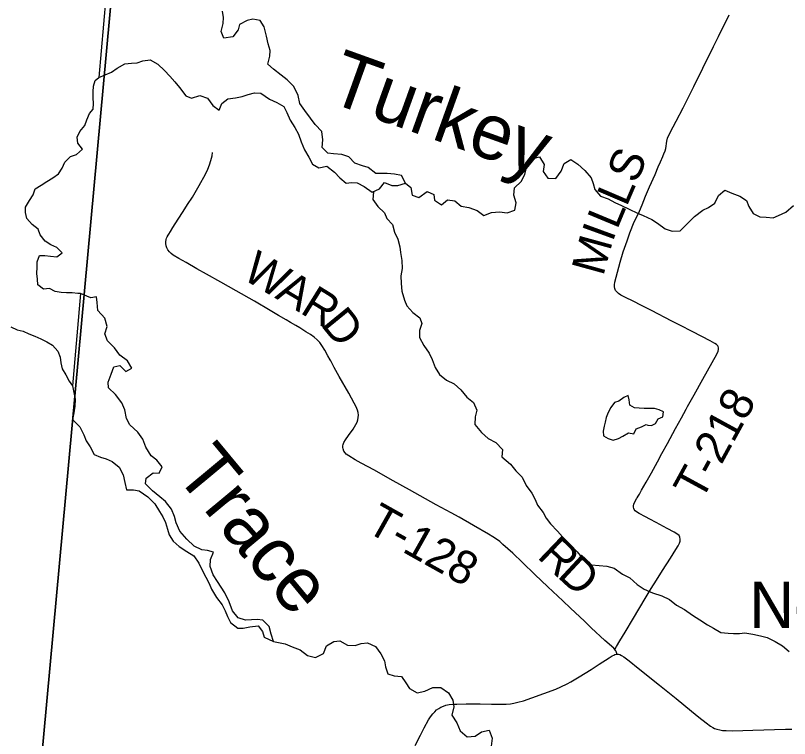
# Model space of a CAD drawing. Extents: x 0 to 34, y 0 to 22.
# Drawn here: x 3.277 to 4.6, y 17.655 to 18.891 of the extents above; entities that cross this region are included whole.
import ezdxf

# ---------------------------------------------------------------- set-up
doc = ezdxf.new("R2010")
doc.units = 0
for name, color, linetype in [('Default', 7, 'Continuous'), ('GM_X_County_Road', 7, 'Continuous'), ('GM_X_Major_Lake', 7, 'Continuous'), ('GM_X_Minor_Lake', 7, 'Continuous'), ('GM_X_Minor_River', 7, 'Continuous'), ('GM_X_Minor_River_Text', 7, 'Continuous'), ('GM_X_Township_Road', 7, 'Continuous'), ('GM_X_Township_Road_Text', 7, 'Continuous'), ('GM_X_Unincorporated_Text', 7, 'Continuous'), ('SH_Cut_Line', 7, 'Continuous')]:
    doc.layers.add(name, color=color, linetype=linetype)

msp = doc.modelspace()

# ---------------------------------------------------------------- linework, layer by layer
at = {"layer": 'Default'}
for points in [[(8.3334, 17.361), (8.3935, 18.0719), (8.4126, 18.2788), (8.4989, 19.2757), (8.562, 20.012), (8.6014, 20.4252), (3.5682, 20.4252), (3.5424, 20.1754), (3.5231, 19.8516), (3.5169, 19.7823), (3.5125, 19.7343), (3.5092, 19.6961), (3.5066, 19.6647), (3.4966, 19.5464), (3.4903, 19.4759), (3.4748, 19.2963), (3.47, 19.2407), (3.2768, 17.1355)], [(3.2768, 17.1355), (3.47, 19.2407)]]:
    msp.add_lwpolyline(points, dxfattribs=at)
at = {"layer": 'GM_X_County_Road'}
for points in [[(3.96, 17.6431), (3.9688, 17.6607), (3.9753, 17.6734), (3.9829, 17.6869), (3.9862, 17.6922), (3.99, 17.6972), (3.9933, 17.701), (3.9966, 17.704), (4.0002, 17.7067), (4.004, 17.7089), (4.0081, 17.7107), (4.0123, 17.7121), (4.0179, 17.7132), (4.0242, 17.714), (4.031, 17.7142), (4.0472, 17.7144), (4.0708, 17.7143), (4.0901, 17.714), (4.105, 17.7139), (4.1155, 17.7142), (4.1228, 17.7147), (4.1283, 17.7156), (4.1355, 17.7172), (4.1449, 17.7199), (4.1591, 17.7245), (4.1801, 17.732), (4.2003, 17.7397), (4.2088, 17.7433), (4.2199, 17.7488), (4.2258, 17.752), (4.2402, 17.7605), (4.2606, 17.7734), (4.2746, 17.7826), (4.2913, 17.7934), (4.2968, 17.7965), (4.2993, 17.7977), (4.3013, 17.7987), (4.3032, 17.7993), (4.3043, 17.7996), (4.3049, 17.7996)], [(4.3049, 17.7996), (4.3063, 17.7996), (4.3073, 17.7995), (4.3099, 17.7988), (4.3128, 17.7974), (4.3165, 17.7949), (4.3255, 17.7882), (4.3409, 17.7756), (4.3778, 17.7463), (4.4058, 17.7236), (4.4325, 17.7022), (4.4449, 17.6919), (4.4571, 17.6823), (4.465, 17.6763), (4.4685, 17.674), (4.4718, 17.6724), (4.4758, 17.671), (4.4805, 17.6698), (4.4853, 17.6691), (4.4915, 17.6687), (4.5032, 17.6686), (4.5374, 17.6696), (4.5927, 17.671), (4.6038, 17.6713)]]:
    msp.add_lwpolyline(points, dxfattribs=at)
at = {"layer": 'GM_X_Major_Lake'}
for p, q in [((3.4324, 18.9394), (3.4192, 18.7851)), ((3.3875, 18.4159), (3.374, 18.2583))]:
    msp.add_line(p, q, dxfattribs=at)
for points in [[(3.5567, 18.7683), (3.5676, 18.7537), (3.5774, 18.7498), (3.5915, 18.7546), (3.6047, 18.75), (3.6137, 18.7377), (3.625, 18.7293), (3.6293, 18.741), (3.6396, 18.7489), (3.6525, 18.7507), (3.6639, 18.7529), (3.6742, 18.7562), (3.6852, 18.7591), (3.6962, 18.7583), (3.7109, 18.7483), (3.7234, 18.7424), (3.7355, 18.7355), (3.7403, 18.7252), (3.7463, 18.7122), (3.7541, 18.6996), (3.7605, 18.6886), (3.7649, 18.6752), (3.7709, 18.6619), (3.7783, 18.6493), (3.7843, 18.6371), (3.7953, 18.6309), (3.8086, 18.6338), (3.8221, 18.6235), (3.8312, 18.6135), (3.8417, 18.6047), (3.8512, 18.6057), (3.8607, 18.6053), (3.8728, 18.5991), (3.8863, 18.5891), (3.8989, 18.595), (3.9077, 18.606), (3.9198, 18.6009), (3.9304, 18.6005), (3.9434, 18.6045), (3.9363, 18.6175), (3.9246, 18.6203), (3.9117, 18.6211), (3.9022, 18.6212), (3.8927, 18.6209), (3.8795, 18.6313), (3.8697, 18.634), (3.8568, 18.6387), (3.8463, 18.6498), (3.8345, 18.6537), (3.8201, 18.6546), (3.8103, 18.6558), (3.8009, 18.6658), (3.8018, 18.6787), (3.8004, 18.6928), (3.7891, 18.705), (3.7812, 18.7157), (3.7715, 18.7287), (3.7625, 18.7406), (3.7596, 18.7543), (3.7525, 18.7699), (3.7408, 18.7814), (3.731, 18.7895), (3.7175, 18.7995), (3.7077, 18.8083), (3.7112, 18.8216), (3.7117, 18.8314), (3.7088, 18.8428), (3.7058, 18.8558), (3.7018, 18.8721), (3.6947, 18.8825), (3.6822, 18.8849), (3.6727, 18.883), (3.6593, 18.8759), (3.6574, 18.8665), (3.6482, 18.8548), (3.633, 18.8526), (3.6281, 18.8637), (3.6317, 18.8777), (3.6321, 18.888), (3.6303, 18.8986)], [(3.4192, 18.7851), (3.4408, 18.7944), (3.4504, 18.8015), (3.4637, 18.8086), (3.4747, 18.8096), (3.4846, 18.8103), (3.4945, 18.814), (3.507, 18.8154), (3.5202, 18.8081), (3.5315, 18.7973), (3.5405, 18.7874), (3.5488, 18.7778), (3.5567, 18.7683)], [(3.4095, 18.731), (3.4097, 18.7409), (3.4096, 18.7508), (3.4095, 18.7607), (3.4097, 18.7702), (3.413, 18.7804), (3.4192, 18.7851)], [(3.3875, 18.4159), (3.3833, 18.416), (3.3734, 18.4174), (3.3639, 18.4173), (3.3545, 18.4179), (3.3446, 18.4197), (3.3345, 18.4245), (3.3246, 18.4233), (3.3149, 18.4311), (3.3144, 18.4407), (3.3128, 18.4502), (3.3138, 18.4608), (3.3137, 18.4703), (3.3174, 18.4809), (3.3269, 18.481), (3.3367, 18.48), (3.347, 18.4789), (3.3566, 18.4855), (3.347, 18.4945), (3.3372, 18.4993), (3.3275, 18.5057), (3.3187, 18.5165), (3.3155, 18.5261), (3.3051, 18.534), (3.2959, 18.5441), (3.2935, 18.5544), (3.2938, 18.5639), (3.3005, 18.5751), (3.3068, 18.5849), (3.3105, 18.595), (3.3206, 18.6012), (3.3302, 18.6074), (3.3403, 18.6136), (3.3503, 18.6206), (3.3563, 18.6303), (3.3611, 18.6408), (3.3709, 18.6504), (3.3808, 18.6536), (3.3909, 18.6628), (3.3829, 18.6729), (3.382, 18.6832), (3.3864, 18.6929), (3.3951, 18.7033), (3.3987, 18.7131), (3.4032, 18.7236), (3.4095, 18.731)], [(3.4292, 18.3471), (3.4335, 18.3596), (3.4291, 18.3737), (3.4174, 18.3871), (3.4164, 18.4004), (3.415, 18.4106), (3.4051, 18.4088), (3.3875, 18.4159)], [(3.2686, 18.359), (3.2795, 18.3538), (3.2897, 18.3516), (3.2994, 18.3472), (3.3096, 18.3428), (3.3201, 18.3387), (3.3302, 18.3335), (3.3399, 18.3275), (3.3491, 18.3174), (3.353, 18.3074)], [(3.374, 18.2583), (3.3785, 18.2355), (3.378, 18.2234), (3.3764, 18.212), (3.374, 18.2006), (3.3864, 18.1883), (3.3935, 18.1742), (3.3976, 18.1643), (3.4043, 18.154), (3.411, 18.141), (3.422, 18.1364), (3.4318, 18.1333), (3.4416, 18.1286), (3.4541, 18.119), (3.4604, 18.106), (3.4633, 18.0927), (3.4663, 18.0805), (3.4784, 18.0804), (3.4879, 18.0788), (3.5026, 18.0684), (3.5146, 18.0566), (3.5228, 18.0436), (3.5284, 18.034), (3.5329, 18.0245), (3.5366, 18.0134), (3.5392, 18.0035), (3.5459, 17.9925), (3.5564, 17.9833), (3.5696, 17.9748), (3.5817, 17.9675), (3.59, 17.9552), (3.5963, 17.9419), (3.6019, 17.9308), (3.6075, 17.9201), (3.6119, 17.9106), (3.6205, 17.8965), (3.6299, 17.8835), (3.6348, 17.8736), (3.6392, 17.8636), (3.6441, 17.8537), (3.6565, 17.8441), (3.666, 17.844), (3.6774, 17.8462), (3.6914, 17.8476), (3.6989, 17.838), (3.7015, 17.8285), (3.7179, 17.8212), (3.7137, 17.8337), (3.71, 17.8467), (3.6995, 17.8574), (3.6896, 17.8586), (3.6802, 17.858), (3.6699, 17.8577), (3.657, 17.8616), (3.6477, 17.8734), (3.6421, 17.8891), (3.6343, 17.9043), (3.6283, 17.9139), (3.6219, 17.9238), (3.6148, 17.9349), (3.6093, 17.9494), (3.6101, 17.9615), (3.6152, 17.9736), (3.605, 17.9767), (3.5951, 17.978), (3.5823, 17.9842), (3.5695, 17.9961), (3.5578, 18.0095), (3.5511, 18.0239), (3.5482, 18.0346), (3.5434, 18.0472), (3.5332, 18.0606), (3.5234, 18.0682), (3.511, 18.0786), (3.4986, 18.0905), (3.4998, 18.1004), (3.5117, 18.1094), (3.5223, 18.1089), (3.5273, 18.1195), (3.5183, 18.131), (3.5085, 18.1383), (3.4995, 18.1532), (3.4944, 18.1669), (3.4857, 18.1791), (3.4718, 18.1914), (3.4666, 18.2021), (3.4637, 18.2169), (3.4585, 18.2291), (3.4476, 18.2432), (3.4356, 18.2547), (3.4349, 18.2646), (3.44, 18.2783), (3.4446, 18.2904), (3.4549, 18.2929), (3.4654, 18.2826), (3.4757, 18.2886), (3.4682, 18.3008), (3.455, 18.3108), (3.4461, 18.3234), (3.4336, 18.3349), (3.4292, 18.3471)], [(3.353, 18.3074), (3.3543, 18.2975), (3.3563, 18.2872), (3.3625, 18.2768), (3.3683, 18.2663), (3.374, 18.2583)]]:
    msp.add_lwpolyline(points, dxfattribs=at)
at = {"layer": 'GM_X_Minor_Lake'}
for points in [[(4.3578, 18.1912), (4.364, 18.1901), (4.3709, 18.1937), (4.3753, 18.202), (4.3833, 18.2053), (4.3846, 18.2136), (4.3771, 18.2171), (4.3688, 18.2196), (4.3604, 18.2194), (4.3513, 18.2196), (4.343, 18.2201), (4.335, 18.2206), (4.3268, 18.2254), (4.3258, 18.2341), (4.3241, 18.2417), (4.3164, 18.2385), (4.3083, 18.2318), (4.3007, 18.2297), (4.2944, 18.2214), (4.2897, 18.2124), (4.2861, 18.2038), (4.2844, 18.1958)], [(4.2844, 18.1958), (4.2828, 18.189), (4.2815, 18.1807), (4.2817, 18.1727), (4.29, 18.1684), (4.2986, 18.1655), (4.3074, 18.168), (4.3151, 18.1724), (4.3243, 18.1779), (4.3334, 18.1759), (4.3377, 18.1849), (4.3465, 18.1881), (4.3546, 18.1918), (4.3578, 18.1912)]]:
    msp.add_lwpolyline(points, dxfattribs=at)
at = {"layer": 'GM_X_Minor_River'}
for points in [[(3.9434, 18.6045), (3.9522, 18.597), (3.9546, 18.5844), (3.9663, 18.5803), (3.9802, 18.5903), (3.9915, 18.5852), (3.9928, 18.5756), (4.0048, 18.5674), (4.0152, 18.5763), (4.0277, 18.5746), (4.0385, 18.5652), (4.0518, 18.5631), (4.0657, 18.5579), (4.0773, 18.5493), (4.0903, 18.5547), (4.104, 18.5556), (4.1173, 18.5538), (4.1303, 18.5585), (4.1324, 18.571), (4.1285, 18.5843), (4.1299, 18.5968), (4.1408, 18.6076), (4.1474, 18.6193), (4.1508, 18.6336), (4.1594, 18.6464), (4.1723, 18.6495), (4.1804, 18.6368), (4.1787, 18.6247), (4.1868, 18.6132), (4.2005, 18.6129), (4.2094, 18.6253), (4.2146, 18.6384), (4.2262, 18.645), (4.2378, 18.6372), (4.2501, 18.6263), (4.2605, 18.614), (4.2641, 18.604), (4.2669, 18.5941), (4.2765, 18.5822), (4.2897, 18.5777), (4.301, 18.5718), (4.3127, 18.5666), (4.3255, 18.5603), (4.3401, 18.5532), (4.3499, 18.5492), (4.3642, 18.5428), (4.3744, 18.5365), (4.3871, 18.5268), (4.3991, 18.5224), (4.4128, 18.5232), (4.4241, 18.5348), (4.4376, 18.5474), (4.4519, 18.5585), (4.4615, 18.5633), (4.4719, 18.5707), (4.4782, 18.5838), (4.489, 18.5924), (4.5014, 18.5876), (4.515, 18.5824), (4.5262, 18.5749), (4.5302, 18.565), (4.5376, 18.5527), (4.5492, 18.5471), (4.5598, 18.5465), (4.5716, 18.5455), (4.5812, 18.5491), (4.5938, 18.555), (4.6069, 18.5665)], [(3.8885, 18.5901), (3.8873, 18.577), (3.8961, 18.5647), (3.9073, 18.5542), (3.9113, 18.5442), (3.921, 18.5338), (3.9245, 18.5208), (3.9303, 18.5089), (3.9335, 18.4956), (3.9348, 18.486), (3.9368, 18.4723), (3.9377, 18.4586), (3.9356, 18.4462), (3.9357, 18.4332), (3.9373, 18.4199), (3.9419, 18.4046), (3.9455, 18.3947), (3.9559, 18.3835), (3.9679, 18.3745), (3.9711, 18.365), (3.9675, 18.3529), (3.9672, 18.3407), (3.9746, 18.3273), (3.9838, 18.3142), (3.9889, 18.3031), (3.9943, 18.2897), (4.0013, 18.2774), (4.0133, 18.268), (4.0268, 18.2617), (4.038, 18.2512), (4.048, 18.2389), (4.0596, 18.2295), (4.0654, 18.2165), (4.0625, 18.2052), (4.0619, 18.1919), (4.0734, 18.1784), (4.0849, 18.1683), (4.0977, 18.1612), (4.1092, 18.1492), (4.1078, 18.1367), (4.1228, 18.1242), (4.132, 18.113), (4.1425, 18.1018), (4.1494, 18.088), (4.1594, 18.0745), (4.1649, 18.0638), (4.1692, 18.0542), (4.1785, 18.0419), (4.1836, 18.0319), (4.1914, 18.0222), (4.2033, 18.0099), (4.2118, 18.0002), (4.2226, 17.9878), (4.2367, 17.9746), (4.2471, 17.9619), (4.2613, 17.9521), (4.2746, 17.9511), (4.2875, 17.9497), (4.3003, 17.9464), (4.3142, 17.9363), (4.3266, 17.9299), (4.3396, 17.9183), (4.3516, 17.9105), (4.3656, 17.9045), (4.3818, 17.8989), (4.3946, 17.8929), (4.4069, 17.8832), (4.4204, 17.8757), (4.4339, 17.8663), (4.4467, 17.8584), (4.4598, 17.8498), (4.4699, 17.8439), (4.4823, 17.8365), (4.4948, 17.8351), (4.5043, 17.8345), (4.5142, 17.8347), (4.5237, 17.8357), (4.5369, 17.8339), (4.5501, 17.8309), (4.5618, 17.8277), (4.5754, 17.8213), (4.5878, 17.8135), (4.5993, 17.8038)], [(3.7179, 17.8212), (3.7377, 17.8171), (3.7498, 17.8119), (3.763, 17.8071), (3.7757, 17.797), (3.7893, 17.7937), (3.8031, 17.8006), (3.8083, 17.8134), (3.8206, 17.8208), (3.8309, 17.8221), (3.8444, 17.815), (3.8573, 17.8144), (3.8676, 17.8176), (3.8783, 17.8189), (3.8922, 17.8125), (3.901, 17.8002), (3.9073, 17.7879), (3.9093, 17.778), (3.9133, 17.7658), (3.9238, 17.7625), (3.9367, 17.7615), (3.9441, 17.7504), (3.95, 17.7407), (3.9631, 17.7336), (3.9761, 17.736), (3.9899, 17.7422), (4.0035, 17.7423), (4.0167, 17.7333), (4.0244, 17.721), (4.0257, 17.7092), (4.0227, 17.6952), (4.0312, 17.6818), (4.037, 17.6684), (4.0486, 17.6579), (4.0626, 17.6595), (4.073, 17.6669), (4.0864, 17.6697), (4.0914, 17.6559), (4.0896, 17.6423)]]:
    msp.add_lwpolyline(points, dxfattribs=at)
at = {"layer": 'GM_X_Township_Road'}
for points in [[(4.3011, 17.8075), (4.3041, 17.8125), (4.3098, 17.822), (4.3186, 17.837), (4.3329, 17.861), (4.3528, 17.8946), (4.3631, 17.9116), (4.3725, 17.9262), (4.3827, 17.9422), (4.3962, 17.9638), (4.4053, 17.9783), (4.4092, 17.9847), (4.4116, 17.9892), (4.4129, 17.9927), (4.413, 17.9963), (4.4124, 17.9994), (4.4109, 18.0022), (4.4073, 18.0054), (4.4026, 18.0081), (4.3904, 18.0144), (4.3718, 18.0244), (4.3609, 18.0303), (4.3537, 18.034), (4.3427, 18.0399), (4.3384, 18.0425), (4.3359, 18.0446), (4.3342, 18.0468), (4.3334, 18.0486), (4.3329, 18.0506), (4.3329, 18.0533), (4.3335, 18.0559), (4.3348, 18.0589), (4.3375, 18.0637), (4.3384, 18.0653), (4.3393, 18.0669), (4.3409, 18.0695), (4.3431, 18.0732), (4.3466, 18.0798), (4.3548, 18.0935), (4.3636, 18.1094), (4.3741, 18.1284), (4.3818, 18.1426), (4.3911, 18.1595), (4.405, 18.1851), (4.4154, 18.2036), (4.4233, 18.2183), (4.4257, 18.2227), (4.4368, 18.2428), (4.4517, 18.2693), (4.4754, 18.3122), (4.4777, 18.3172), (4.4784, 18.3202), (4.4785, 18.3232), (4.478, 18.3253), (4.4772, 18.3267), (4.4752, 18.3286), (4.4722, 18.3306), (4.4641, 18.3351), (4.4348, 18.3505), (4.4122, 18.3617), (4.3989, 18.3685), (4.3637, 18.387), (4.3465, 18.3957), (4.3327, 18.4027), (4.3194, 18.4094), (4.3115, 18.4134), (4.3072, 18.4161), (4.3044, 18.4188), (4.3025, 18.4214), (4.3011, 18.4244), (4.3005, 18.4277), (4.3004, 18.4309), (4.3012, 18.4354), (4.3104, 18.4696), (4.3157, 18.4874), (4.322, 18.5063), (4.3268, 18.5197), (4.3345, 18.5386), (4.3399, 18.5493), (4.3431, 18.5565), (4.3478, 18.5677), (4.3538, 18.5826), (4.3604, 18.5986), (4.3699, 18.6197), (4.3755, 18.6328), (4.379, 18.6413), (4.3832, 18.6503), (4.3839, 18.652), (4.3852, 18.6548), (4.3873, 18.6598), (4.3883, 18.6639), (4.3901, 18.6762), (4.3915, 18.6817), (4.3938, 18.6876), (4.4007, 18.7008), (4.406, 18.7106), (4.4181, 18.7337), (4.4274, 18.7519), (4.4362, 18.7697), (4.4519, 18.8014), (4.4701, 18.8381), (4.4786, 18.8554), (4.4966, 18.8923)], [(4.3011, 17.8075), (4.2993, 17.8096), (4.2839, 17.823), (4.2608, 17.8447), (4.2491, 17.8558), (4.2256, 17.878), (4.2121, 17.8908), (4.1868, 17.9146), (4.1647, 17.9356), (4.1432, 17.9562), (4.1268, 17.9719), (4.11, 17.9868), (4.1044, 17.9919), (4.0988, 17.9959), (4.0925, 18.0001), (4.085, 18.0045), (4.0593, 18.0192), (4.0349, 18.0334), (4.0213, 18.0413), (3.996, 18.055), (3.9504, 18.0803), (3.9221, 18.0958), (3.9054, 18.1054), (3.8902, 18.1138), (3.8678, 18.1258), (3.8574, 18.1316), (3.8462, 18.1384), (3.8421, 18.1414), (3.8399, 18.1438), (3.8381, 18.1466), (3.8367, 18.1502), (3.8362, 18.1528), (3.8362, 18.1555), (3.8367, 18.158), (3.8379, 18.1611), (3.8408, 18.166), (3.8458, 18.1732), (3.8536, 18.1843), (3.8586, 18.1921), (3.8605, 18.1959), (3.8618, 18.1999), (3.8626, 18.204), (3.8628, 18.2082), (3.8624, 18.2124), (3.8613, 18.2165), (3.8591, 18.2222), (3.8558, 18.2288), (3.8464, 18.2455), (3.83, 18.2741), (3.8215, 18.2893), (3.8154, 18.3008), (3.8143, 18.3029), (3.8107, 18.3093), (3.8052, 18.3189), (3.8002, 18.3274), (3.7966, 18.3324), (3.7924, 18.3369), (3.7874, 18.3413), (3.7809, 18.346), (3.773, 18.3507), (3.7625, 18.3571), (3.7556, 18.3613), (3.7465, 18.3665), (3.7391, 18.371), (3.7263, 18.3786), (3.7117, 18.3867), (3.6852, 18.4027), (3.6536, 18.4208), (3.6278, 18.4354), (3.6034, 18.4489), (3.5865, 18.4583), (3.5683, 18.4688), (3.5557, 18.4757), (3.5462, 18.4816), (3.5426, 18.4844), (3.5398, 18.487), (3.537, 18.4905), (3.5352, 18.4941), (3.5341, 18.4974), (3.5335, 18.5013), (3.5336, 18.5043), (3.5344, 18.5084), (3.535, 18.5104), (3.536, 18.5131), (3.5376, 18.5156), (3.5389, 18.5177), (3.5418, 18.5223), (3.5456, 18.5287), (3.5547, 18.5429), (3.5634, 18.5563), (3.5709, 18.568), (3.5791, 18.5807), (3.5905, 18.6005), (3.6012, 18.6202), (3.6053, 18.6284), (3.6084, 18.6358), (3.6108, 18.6434), (3.6126, 18.6511), (3.6136, 18.6572)], [(4.3049, 17.7996), (4.3047, 17.8005), (4.304, 17.8025), (4.3034, 17.804), (4.3029, 17.805), (4.3023, 17.8059), (4.3011, 17.8075)]]:
    msp.add_lwpolyline(points, dxfattribs=at)
at = {"layer": 'SH_Cut_Line'}
for points in [[(3.5682, 20.4252), (2.2621, 20.4252), (2.2621, 13.6252), (2.9696, 13.6252), (3.0429, 14.4692), (3.0457, 14.4958), (3.0617, 14.6751), (3.1343, 15.4291), (3.1974, 16.1596), (3.2667, 16.919), (3.2768, 17.1355), (3.47, 19.2407), (3.4748, 19.2963), (3.4903, 19.4759), (3.4966, 19.5464), (3.5066, 19.6647), (3.5092, 19.6961), (3.5125, 19.7343), (3.5169, 19.7823), (3.5231, 19.8516), (3.5424, 20.1754)], [(2.9696, 13.6252), (9.0621, 13.6252), (9.0621, 20.4252), (3.5682, 20.4252), (3.5424, 20.1754), (3.5231, 19.8516), (3.5169, 19.7823), (3.5125, 19.7343), (3.5092, 19.6961), (3.5066, 19.6647), (3.4966, 19.5464), (3.4903, 19.4759), (3.4748, 19.2963), (3.47, 19.2407), (3.2768, 17.1355), (3.2667, 16.919), (3.1974, 16.1596), (3.1343, 15.4291), (3.0617, 14.6751), (3.0457, 14.4958), (3.0429, 14.4692)]]:
    msp.add_lwpolyline(points, close=True, dxfattribs=at)

# ---------------------------------------------------------------- texts
at = {"layer": 'GM_X_Minor_River_Text'}
for s, rotation, p in [('Turkey', 340.2292, (3.8066, 18.7455)), ('Trace', 309.7292, (3.5464, 18.1082))]:
    msp.add_text(s, height=0.09469, rotation=rotation, dxfattribs=at).set_placement(p)
at = {"layer": 'GM_X_Township_Road_Text'}
for s, height, rotation, p in [('S', 0.0568, 66.8516, (4.3379, 18.6021)), ('L', 0.0568, 66.8678, (4.3212, 18.563)), ('L', 0.0568, 67.4052, (4.305, 18.5239)), ('I', 0.0568, 69.9775, (4.2972, 18.5026)), ('M', 0.0568, 74.6169, (4.2812, 18.4443)), ('W', 0.0568, 329.3807, (3.6619, 18.4427)), ('A', 0.0568, 329.3595, (3.7185, 18.4092)), ('R', 0.0568, 328.2089, (3.7613, 18.3838)), ('D', 0.0568, 309.1918, (3.7972, 18.3625)), ('T-218', 0.05682, 61.3464, (4.4489, 18.059)), ('T-128', 0.05682, 330.7049, (3.8732, 18.0107)), ('R', 0.0568, 316.2228, (4.1668, 17.9654)), ('D', 0.0568, 317.0787, (4.2012, 17.9325))]:
    msp.add_text(s, height=height, rotation=rotation, dxfattribs=at).set_placement(p)
at = {"layer": 'GM_X_Unincorporated_Text'}
msp.add_text('North Kingman', height=0.078977, rotation=0, dxfattribs=at).set_placement((4.5313, 17.8442))

doc.saveas('drawing.dxf')
